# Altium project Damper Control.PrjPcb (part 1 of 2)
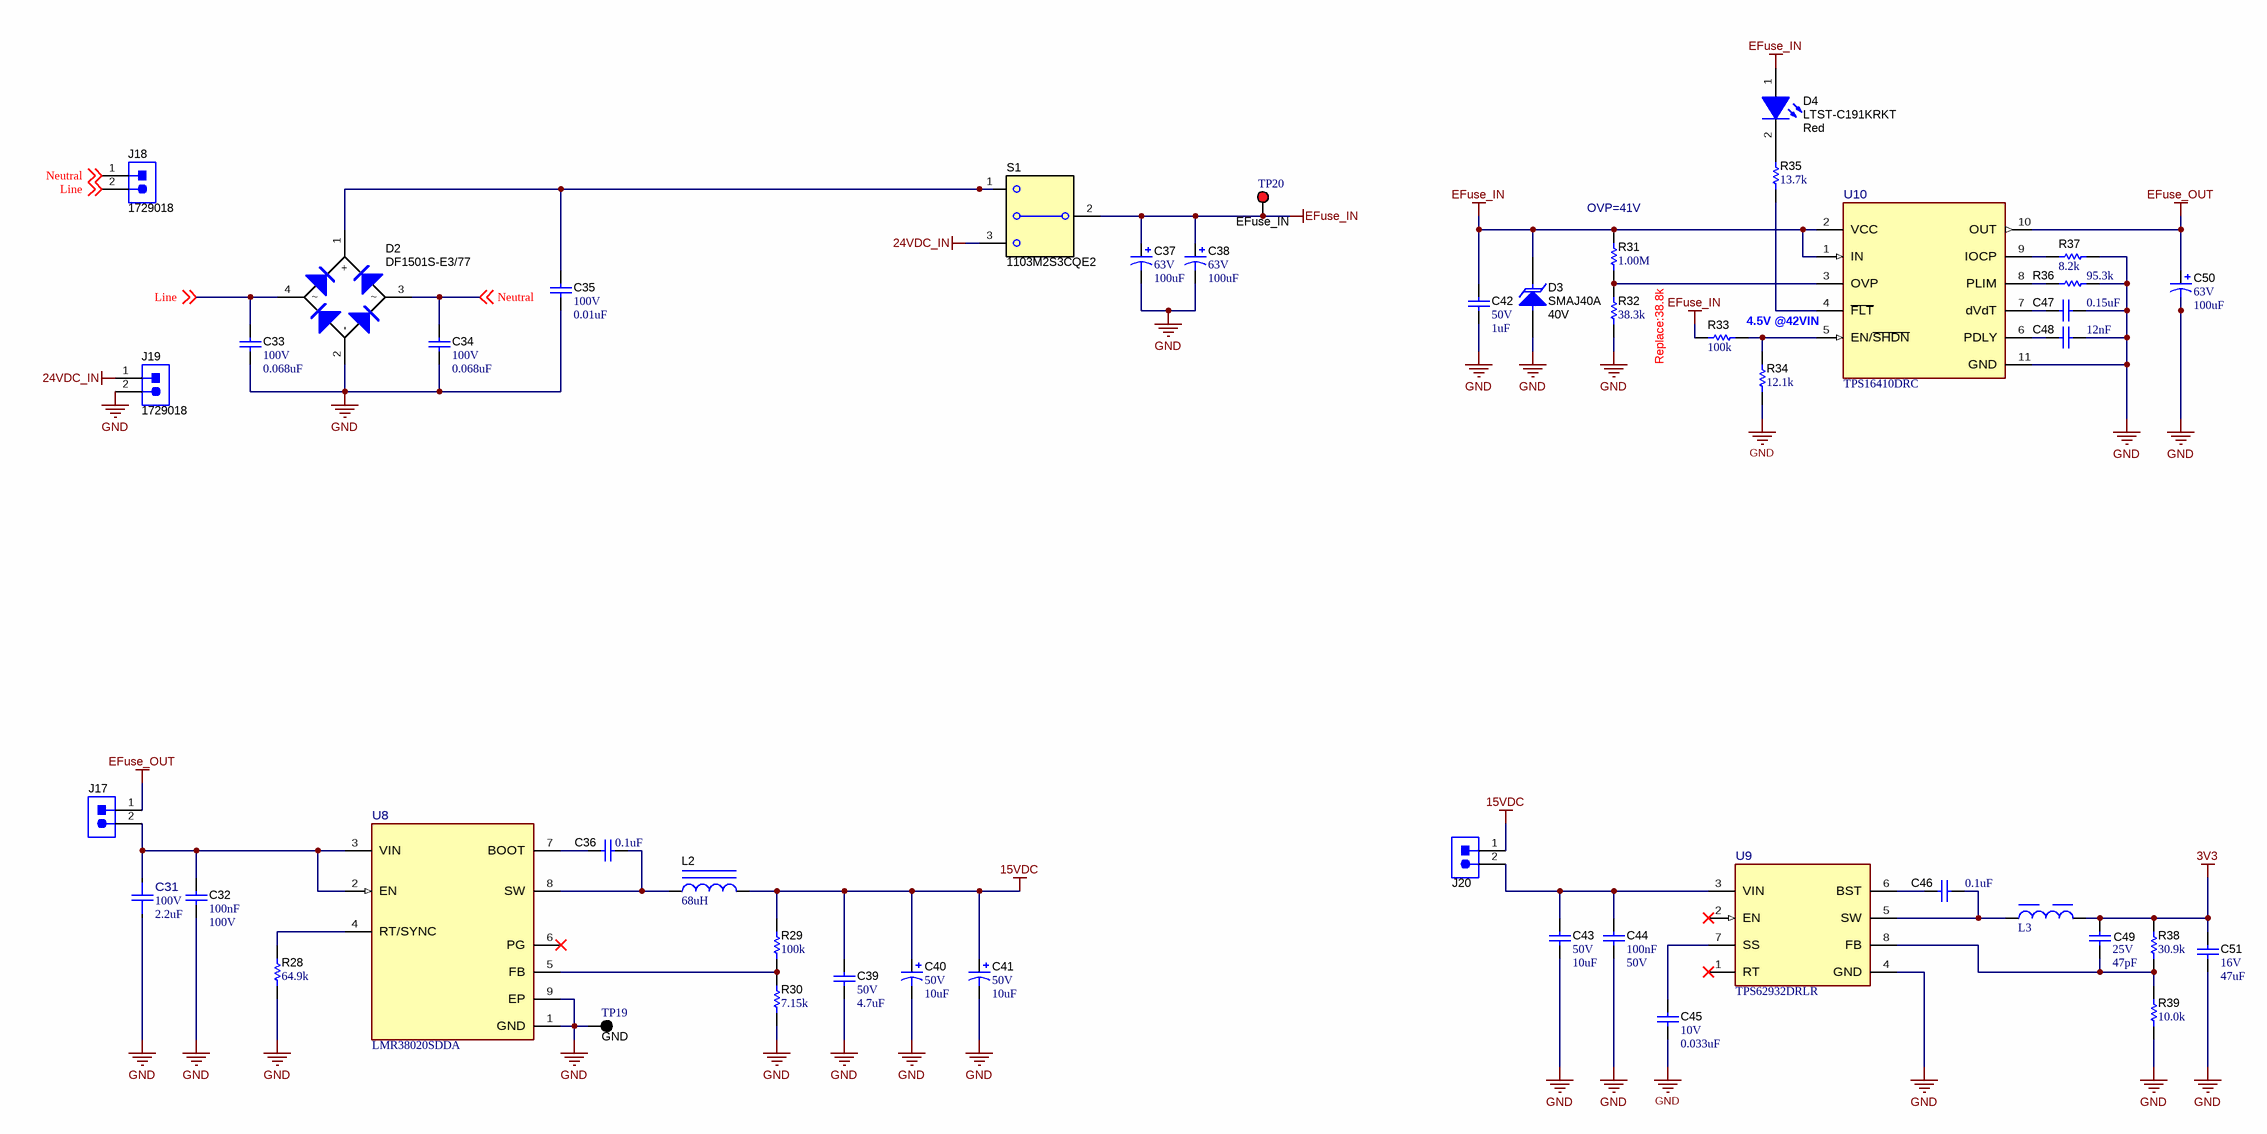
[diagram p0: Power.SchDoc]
CopyrightYear: 2018; PCB_Layout: Who did the Layout?; PCB_Rev: E1; PRJ_Customer: Public Release; PRJ_Engineer: Enter name of project lead; PRJ_Number: TIDA-010950; PRJ_Title: Damper and Electronic Expansion Valve Control with Position Sensing; SCH_Rev: E1; TechSupport: http://www.ti.com/support; TID: N/A
4 sheets, 208 parts. Net scope: global (net labels, ports and power ports of the same name join across sheets).
Board file: Damper Control.PcbDoc
Sheets:
  Power.SchDoc
  Damper Control_BlankSheet.SchDoc
  Interface and Peripherals.SchDoc
  Damper Control_Hardware.SchDoc

## Sheet Power.SchDoc
size A2; Date: Not shown in title block; ApprovedBy: Not shown in title block; CheckedBy: Not shown in title block; Author: Not shown in title block; CompanyName: Not shown in title block; Engineer: Not shown in title block; Organization: Not shown in title block; Address1: Not shown in title block; Address2: Not shown in title block; Address3: Not shown in title block; Address4: Not shown in title block; DocumentNumber: 2; Revision: Use project parameter SCH_Rev; SheetNumber: 2; SheetTotal: 5; PageSetup: Record=PageOptions¦CenterHorizontal=True¦CenterVertical=True¦PrintScale=0.69¦XCorrection=1.00¦YCorrection=1.00¦PrintKind=0¦BorderSize=5000000¦LeftOffset=0¦BottomOffset=0¦Orientation=2¦PaperLength=1000¦PaperWidth=1000¦Scale=100¦PaperSource=15¦PrintQuality=600¦MediaType=1¦DitherType=10¦PaperKind=Letter¦PrintScaleMode=1

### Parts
C31  VDC_V: 100V  ValueDisplayed: 2.2uF  [FP-C3225X7R2A225K230AB_1210-MFG]  (hidden comment: C3225X7R2A225K230AB)
C32  Cap_F: 100nF  VDC_V: 100V  [0805_HV]  (hidden comment: C2012X7R2A104K125AA)
C33  VDC_V: 100V  ValueDisplayed: 0.068uF  [0603]  (hidden comment: C1608X7S2A683K080AB)
C34  VDC_V: 100V  ValueDisplayed: 0.068uF  [0603]  (hidden comment: C1608X7S2A683K080AB)
C35  VDC_V: 100V  ValueDisplayed: 0.01uF  [0402]  (hidden comment: CGA2B3X7S2A103K050BB)
C36  ValueDisplayed: 0.1uF  [0402]  (hidden comment: GRM155R71C104KA88D)
C37  VDC_V: 63V  ValueDisplayed: 100uF  [SM_RADIAL_G]  (hidden comment: EEE-FK1J101P)
C38  VDC_V: 63V  ValueDisplayed: 100uF  [SM_RADIAL_G]  (hidden comment: EEE-FK1J101P)
C39  VDC_V: 50V  ValueDisplayed: 4.7uF  [0805_HV]  (hidden comment: C2012X5R1H475K125AB)
C40  VDC_V: 50V  ValueDisplayed: 10uF  [CAPSMT_62_F61]  (hidden comment: 50SVPF10M)
C41  VDC_V: 50V  ValueDisplayed: 10uF  [CAPSMT_62_F61]  (hidden comment: 50SVPF10M)
C42  VDC_V: 50V  ValueDisplayed: 1uF  [0603]  (hidden comment: C1608X5R1H105K080AB)
C43  VDC_V: 50V  ValueDisplayed: 10uF  [1206_180]  (hidden comment: C3216X5R1H106K160AB)
C44  Cap_F: 100nF  VDC_V: 50V  [0603]  (hidden comment: CGA3E2X7R1H104K080AA)
C45  VDC_V: 10V  ValueDisplayed: 0.033uF  [0402]  (hidden comment: GRM155R71A333KA01D)
C46  ValueDisplayed: 0.1uF  [0402]  (hidden comment: GRM155R71A104KA01D)
C47  ValueDisplayed: 0.15uF  [0603]  (hidden comment: C1608X5R1H154K080AB)
C48  Cap_F: 12nF  [0603]  (hidden comment: GRM188R71H123KA01D)
C49  VDC_V: 25V  ValueDisplayed: 47pF  [0201_033]  (hidden comment: GRM0335C1E470JA01D)
C50  VDC_V: 63V  ValueDisplayed: 100uF  [CAPSMT_62_KE0]  (hidden comment: EMVH630ARA101MKE0S)
C51  VDC_V: 16V  ValueDisplayed: 47uF  [1210_270]  (hidden comment: GRM32ER61C476KE15L)
D2  DF1501S-E3/77  [DF-S]
D3  SMAJ40A  value 40V  [SMA]
D4  LTST-C191KRKT  value Red  [LTST-C191_Red]
J17  M20-8770246  [Harwin_M20-87702]  (value not drawn)
J18  1729018  [Phoenix_1729018]
J19  1729018  [Phoenix_1729018]
J20  M20-8770246  [Harwin_M20-87702]  (value not drawn)
L2  ValueDisplayed: 68uH  [MSS1210]  (hidden comment: MSS1210-683ME)
L3  744325780  [WE-HCI_1050]  (value not drawn)
R28  ValueDisplayed: 64.9k  [0603]  (hidden comment: CRCW060364K9FKEA)
R29  ValueDisplayed: 100k  [0402]  (hidden comment: CRCW0402100KFKED)
R30  ValueDisplayed: 7.15k  [0402]  (hidden comment: CRCW04027K15FKED)
R31  ValueDisplayed: 1.00M  [0603]  (hidden comment: MCT06030C1004FP500)
R32  ValueDisplayed: 38.3k  [0402]  (hidden comment: CRCW040238K3FKED)
R33  ValueDisplayed: 100k  [0603]  (hidden comment: CRCW0603100KJNEA)
R34  ValueDisplayed: 12.1k  [0603]  (hidden comment: CRCW060312K1FKEA)
R35  ValueDisplayed: 13.7k  [0805_HV]  (hidden comment: CRCW080513K7FKEA)
R36  ValueDisplayed: 95.3k  [0603]  (hidden comment: CRCW060395K3FKEA)
R37  ValueDisplayed: 8.2k  [0603]  (hidden comment: CRCW06038K20JNEA)
R38  ValueDisplayed: 30.9k  [0402]  (hidden comment: CRCW040230K9FKED)
R39  ValueDisplayed: 10.0k  [0402]  (hidden comment: CRCW040210K0FKED)
S1  1103M2S3CQE2  [SW_1103M2S3CQE2]
TP19  GND  [Keystone5001]
TP20  EFuse_IN  [Keystone5000]
U8  LMR38020SDDA  [DDA0008E-MFG]
U9  TPS62932DRLR  [DRL0008A-MFG]
U10  TPS16410DRC  [DRC0010J-MFG]

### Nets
3V3: C49.1 C51.1 L3.2 R38.2
15VDC: C39.1 C40.1(+) C41.1(+) J20.1 L2.2 R29.2
24VDC_IN: J19.1 S1.3
EFuse_IN: C37.1(+) C38.1(+) C42.1 D3.1(K) D4.1(A) R31.2 R33.1 S1.2(COM) TP20.1 U10.1(IN) U10.2(VCC)
EFuse_OUT: C50.1(+) J17.1 U10.10(OUT)
GND: C31.1 C32.2 C33.2 C34.2 C35.2 C37.2(-) C38.2(-) C39.2 C40.2(-) C41.2(-) C42.2 C43.2 C44.2 C45.2 C47.1 C48.1 C50.2(-) C51.2 D2.2(-) D3.2(A) J19.2 R28.1 R30.1 R32.1 R34.1 R36.2 R37.2 R39.1 TP19.1 U8.1(GND) U8.9(EP) U9.4(GND) U10.11(GND)
Line: C33.1 D2.4 J18.2 ; off-sheet Line
Neutral: C34.1 D2.3 J18.1 ; off-sheet Neutral
NetC31_2: C31.2 C32.1 J17.2 U8.2(EN) U8.3(VIN)
NetC35_1: C35.1 D2.1(+) S1.1
NetC36_1: C36.1 L2.1 U8.8(SW)
NetC36_2: C36.2 U8.7(BOOT)
NetC43_1: C43.1 C44.1 J20.2 U9.3(VIN)
NetC45_1: C45.1 U9.7(SS)
NetC46_1: C46.1 L3.1 U9.5(SW)
NetC46_2: C46.2 U9.6(BST)
NetC47_2: C47.2 U10.7(dVdT)
NetC48_2: C48.2 U10.6(PDLY)
NetC49_2: C49.2 R38.1 R39.2 U9.8(FB)
NetD4_2: D4.2(K) R35.2
NetR28_2: R28.2 U8.4(RT/SYNC)
NetR29_1: R29.1 R30.2 U8.5(FB)
NetR31_1: R31.1 R32.2 U10.3(OVP)
NetR33_2: R33.2 R34.2 U10.5(EN/~{SHDN})
NetR35_1: R35.1 U10.4(~{FLT})
NetR36_1: R36.1 U10.8(PLIM)
NetR37_1: R37.1 U10.9(IOCP)

Not connected (* = marked no-connect by the designer): U8 6(PG)*; U9 1(RT)* 2(EN)*

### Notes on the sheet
- (near R31) OVP=41V
- (near R33) 4.5V @42VIN
- Replace:38.8k

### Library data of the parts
C31 = CMP-0095533-2: CAP, CERM, 2.2 uF, 100 V, +/- 10%, X7R, 1210; Manufacturer: TDK; AEC Qualified: No; Value: 2.2µF; Tolerance_%: 0.1%; TempCo: 0.15; SizeZ_mm: 2.5mm
C32 = CMP-0007886-2: CAP, CERM, 0.1 uF, 100 V, +/- 10%, X7R, 0805; Manufacturer: TDK; TaMin_C: -55°C; ESR_ohm: 20.726m; Polarized: N; SizeAreaWB_mm2: 6.75; Value1: 0.020726 ohm; U/M: EA; Value: 0.1uF; TaMax_C: 125°C; SizeZ_mm: 1.45; SizeX_mm: 2; SizeY_mm: 1.25; Cap_Case: 0805; SizeArea_mm2: 2.5; IRMS_A: 1.456A; AEC Category: Q200
C33 C34 = CMP-0007061-4: CAP, CERM, 0.068 uF, 100 V, +/- 10%, X7S, 0603; Manufacturer: TDK; TaMin_C: -55°C; ESR_ohm: 74.084m; Polarized: N; SizeAreaWB_mm2: 4.68; Value1: 0.074084 ohm; U/M: EA; TaMax_C: 125°C; SizeZ_mm: 1; SizeX_mm: 1.6; SizeY_mm: 0.8; SizeArea_mm2: 1.28; Cap_F: 68nF; IRMS_A: 619.09mA; AEC Category: Q200
C35 = CMP-0006333-2: CAP, CERM, 0.01 uF, 100 V, +/- 10%, X7S, AEC-Q200 Grade 1, 0402; Manufacturer: TDK; TaMin_C: -55°C; ESR_ohm: 0.4102; Polarized: N; SizeAreaWB_mm2: 3; Value1: 0.410191 ohm; U/M: EA; Value: 0.01uF; TaMax_C: 125°C; SizeZ_mm: 0.6; SizeX_mm: 1; SizeY_mm: 0.5; AEC Qualified: Y; Cap_F: 10nF; IRMS_A: 291.729mA; AEC Category: Q200
C36 = CMP-0006641-2: CAP, CERM, 0.1 uF, 16 V, +/- 10%, X7R, 0402; Manufacturer: MuRata; TaMin_C: -55°C; Polarized: N; SizeAreaWB_mm2: 3; Value1: Unknown; U/M: EA; Value: 0.1uF; TaMax_C: 125°C; SizeZ_mm: 0.6; SizeX_mm: 1; SizeY_mm: 0.5; Value2: 16V; Cap_F: 100nF; AEC Category: Q200
C37 C38 = CMP-0011188-2: CAP, AL, 100 uF, 63 V, +/- 20%, 0.35 ohm, AEC-Q200 Grade 2, SMD; Manufacturer: Panasonic; TaMin_C: -55°C; ESR_ohm: 0.35; Polarized: Y; SizeAreaWB_mm2: 172.2; U/M: EA; Value: 100uF; TaMax_C: 105°C; SizeZ_mm: 10.2; SizeX_mm: 12; SizeY_mm: 10.3; Cap_Case: G; SizeArea_mm2: 123.6; CompType: Capacitor; Cap_F: 100µF; IRMS_A: 400mA; AEC Grade: 2; AEC Category: Q200
C39 = CMP-0007840-2: CAP, CERM, 4.7 uF, 50 V, +/- 10%, X5R, 0805; Manufacturer: TDK; TaMin_C: -55°C; ESR_ohm: 2.346m; Polarized: N; SizeAreaWB_mm2: 6.75; Value1: 0.002346 ohm; U/M: EA; Value: 4.7uF; TaMax_C: 85°C; SizeZ_mm: 1.45; SizeX_mm: 2; SizeY_mm: 1.25; Cap_Case: 0805; SizeArea_mm2: 2.5; Cap_F: 4.7µF; IRMS_A: 4.2602A; AEC Category: Q200
C40 C41 = CMP-0012141-3: CAP, Aluminum Polymer, 10 uF, 50 V, +/- 20%, 0.04 ohm, F61 SMD; Manufacturer: Panasonic; TaMin_C: -55°C; ESR_ohm: 40m; Polarized: Y; SizeAreaWB_mm2: 73.96; Value: 10uF; TaMax_C: 105°C; SizeZ_mm: 5.8; SizeX_mm: 6.6; SizeArea_mm2: 43.56; CompType: Capacitor; Cap_F: 10µF; IRMS_A: 2.5A; AEC Category: Q200
C42 = CMP-0007011-5: CAP, CERM, 1 uF, 50 V, +/- 10%, X5R, 0603; Manufacturer: TDK; TaMin_C: -55°C; ESR_ohm: 5.522m; Polarized: N; SizeAreaWB_mm2: 4.68; Value1: 0.005522 ohm; U/M: EA; Value: 1uF; TaMax_C: 85°C; SizeZ_mm: 1; SizeX_mm: 1.6; SizeY_mm: 0.8; SizeArea_mm2: 1.28; Cap_F: 1µF; IRMS_A: 2.2162A; AEC Category: Q200
C43 = CMP-0008658-2: CAP, CERM, 10 uF, 50 V, +/- 10%, X5R, 1206; Manufacturer: TDK; TaMin_C: -55°C; ESR_ohm: 2.229m; Polarized: N; SizeAreaWB_mm2: 10.92; Value1: 0.002229 ohm; U/M: EA; Value: 10uF; TaMax_C: 85°C; SizeZ_mm: 1.8; SizeX_mm: 3.2; SizeY_mm: 1.6; SizeArea_mm2: 5.12; Cap_F: 10µF; IRMS_A: 4.8593A; AEC Category: Q200
C44 = CMP-0007078-4: CAP, CERM, 0.1 uF, 50 V, +/- 10%, X7R, AEC-Q200 Grade 1, 0603; Manufacturer: TDK; TaMin_C: -55°C; ESR_ohm: 29.6m; Polarized: N; SizeAreaWB_mm2: 4.68; Value1: 0.0296 ohm; U/M: EA; Value: 0.1uF; TaMax_C: 125°C; SizeZ_mm: 1; SizeX_mm: 1.6; SizeY_mm: 0.8; SizeArea_mm2: 1.28; AEC Qualified: Y; IRMS_A: 971.99mA; AEC Category: Q200
C45 = CMP-0006632-2: CAP, CERM, 0.033 uF, 10 V, +/- 10%, X7R, 0402; Manufacturer: MuRata; TaMin_C: -55°C; Polarized: N; SizeAreaWB_mm2: 3; Value1: Unknown; U/M: EA; TaMax_C: 125°C; SizeZ_mm: 0.6; SizeX_mm: 1; SizeY_mm: 0.5; Cap_F: 33nF; AEC Category: Q200
C46 = CMP-0006629-2: CAP, CERM, 0.1 uF, 10 V, +/- 10%, X7R, 0402; Manufacturer: MuRata; TaMin_C: -55°C; Polarized: N; SizeAreaWB_mm2: 3; Value1: Unknown; U/M: EA; Value: 0.1uF; TaMax_C: 125°C; SizeZ_mm: 0.6; SizeX_mm: 1; SizeY_mm: 0.5; Value2: 10V; Cap_F: 100nF; AEC Category: Q200
C47 = CMP-0007012-5: CAP, CERM, 0.15 uF, 50 V, +/- 10%, X5R, 0603; Manufacturer: TDK; TaMin_C: -55°C; ESR_ohm: 28.863m; Polarized: N; SizeAreaWB_mm2: 4.68; Value1: 0.028863 ohm; U/M: EA; Value: 0.15uF; TaMax_C: 85°C; SizeZ_mm: 1; SizeX_mm: 1.6; SizeY_mm: 0.8; Value2: 50V; SizeArea_mm2: 1.28; Cap_F: 150nF; IRMS_A: 978.809mA; AEC Category: Q200
C48 = CMP-0007436-4: CAP, CERM, 0.012 uF, 50 V, +/- 10%, X7R, 0603; Manufacturer: MuRata; TaMin_C: -55°C; Polarized: N; SizeAreaWB_mm2: 4.68; Value1: Unknown; U/M: EA; TaMax_C: 125°C; SizeZ_mm: 1; SizeX_mm: 1.6; SizeY_mm: 0.8; Value2: 50V; SizeArea_mm2: 1.28; AEC Category: Q200
C49 = CMP-0009662-3: CAP, CERM, 47 pF, 25 V, +/- 5%, C0G/NP0, 0201; Manufacturer: MuRata; TaMin_C: -55°C; Polarized: N; SizeAreaWB_mm2: 2.08; Value1: Unknown; U/M: EA; Value: 47pF; TaMax_C: 125°C; SizeZ_mm: 0.33; SizeX_mm: 0.6; SizeY_mm: 0.3; Cap_Case: 0201; SizeArea_mm2: 0.18; AEC Category: Q200
C50 = CMP-0011330-2: CAP, AL, 100 uF, 63 V, +/- 20%, 0.25 ohm, SMD; Manufacturer: Chemi-Con; TaMin_C: -40°C; ESR_ohm: 0.25; Polarized: Y; SizeAreaWB_mm2: 225; U/M: EA; Value: 100uF; TaMax_C: 125°C; SizeZ_mm: 13.5; SizeX_mm: 13; Cap_Case: KE0; SizeArea_mm2: 169; CompType: Capacitor; Cap_F: 100µF; IRMS_A: 500mA; AEC Category: Q200
C51 = CMP-0009211-2: CAP, CERM, 47 uF, 16 V, +/- 10%, X5R, 1210; Manufacturer: MuRata; TaMin_C: -55°C; Polarized: N; SizeAreaWB_mm2: 14.7; Value1: Unknown; U/M: EA; Value: 47uF; TaMax_C: 85°C; SizeZ_mm: 2.7; SizeX_mm: 3.2; SizeY_mm: 2.5; Cap_Case: 1210; SizeArea_mm2: 8; Cap_F: 47µF; AEC Category: Q200
D2 = CMP-0029239-3: Diode, Switching-Bridge, 100 V, 1.5 A, DF-S; Manufacturer: Vishay-Semiconductor; Green_REACh: Incomplete; Value1: 1.5A; SizeAreaWB_mm2: 98.794; Vr_V: 100V; SizeZ_mm: 3.4; AEC Category: Q101; Value: 100V; TJmax_C: 150°C; Vf_V: 1.1V; SizeArea_mm2: 62.974; SizeX_mm: 7.4; SizeY_mm: 8.51; Green_Lifecycle: Not Set
D3 = CMP-0084964-1: Diode, TVS, Uni, 40 V, 64.5 Vc, 400 W, 6.2 A, SMA; Manufacturer: Littelfuse; Ipp: 6.2A; Ppk: 400W; Vbr_Min: 44.4V; AEC Category: Q101; SizeAreaWB_mm2: 37.3428; SizeX_mm: 5.59; SizeArea_mm2: 16.3228; AEC Qualified: N; Value1: 64.5V; SizeY_mm: 2.92; RJA_CperW: 120; SizeZ_mm: 2.87; Vbr_Max: 49.1V
D4 = CMP-0002950-3: LED, Red, SMD; Manufacturer: Lite-On; Value2: 2V; Type: AlInGaP; Ir_A: 10µA; Angle: 130; Value1: 0.075W; Vr_V: 5V; Tjmax_C: 85°C; Power_TotalModule: 75mW; Io_A: 20mA
J17 J20 = CMP-0075288-1: Header, 2.54mm, 2x1, Tin,  SMT; Manufacturer: Harwin; CNHeader: True; Current_A: 3A; Shrouded: N; Gender: Male; Voltage_V: 250V; Row_Count: 1; Pitch_mm: 2.54; CT: False; Cert_UL: Y
J18 J19 = CMP-0055486-1: TERM BLOCK 2POS 5mm, TH; Manufacturer: Phoenix Contact; CT: TRUE; Green_REACh: Incomplete; CompType: Terminal Block; CNHeader: FALSE; Green_Lifecycle: Not Set
L2 = CMP-0061458-2: Inductor, Shielded, Ferrite, 68 uH, 4.3 A, 0.074 ohm, SMD; Manufacturer: Coilcraft; Isat: 4.9A @ 30% inductance drop; Irms: 4.3A @ 40C rise; Green_Lifecycle: Not Set; SizeAreaWB_mm2: 204.49; DCR_ohm: 74m; Green_REACh: Incomplete; Value: 68uH; Imax_A: 4.3A; SizeZ_mm: 10; SizeX_mm: 12.3; SizeArea_mm2: 151.29; Ind_H: 68µH; AEC Category: Q200
L3 = CMP-0098677-1: WE-HCI SMT Flat Wire High Current Inductor, size 1050, 7.8uH, 10.7A, 13.6mOhm; Manufacturer: Wurth Elektronik; Material: Superflux; Case/Size Code: 1050; Saturation Current: 9.5A; Self Resonant Frequency: 23MHz
R28 = CMP-0022544-4: RES, 64.9 k, 1%, 0.1 W, AEC-Q200 Grade 0, 0603; Manufacturer: Vishay-Dale; Power_W: 100mW; TempCo: 100 ppm/C; Value_Code: 64k9; Value: 64.9k; EIA_Code: E96; SizeX_mm: 1.6; SizeY_mm: 0.8; SizeZ_mm: 1; Value2: 0.1W; SizeArea_mm2: 1.28; AEC Qualified: Y; VDC_V: 75V; AEC Category: Q200; AEC Grade: 0
R29 = CMP-0025950-3: RES, 100 k, 1%, 0.063 W, AEC-Q200 Grade 0, 0402; Manufacturer: Vishay-Dale; Power_W: 63mW; TempCo: 100 ppm/C; Value: 100k; EIA_Code: E96; SizeX_mm: 1; SizeY_mm: 0.5; SizeZ_mm: 0.6; Value2: 0.063W; AEC Qualified: Y; VDC_V: 50V; AEC Category: Q200; AEC Grade: 0
R30 = CMP-0026553-2: RES, 7.15 k, 1%, 0.063 W, AEC-Q200 Grade 0, 0402; Manufacturer: Vishay-Dale; Power_W: 63mW; TempCo: 100 ppm/C; Value_Code: 7k15; Value: 7.15k; EIA_Code: E96; SizeX_mm: 1; SizeY_mm: 0.5; SizeZ_mm: 0.6; Value2: 0.063W; AEC Qualified: Y; VDC_V: 50V; AEC Category: Q200; AEC Grade: 0
R31 = CMP-0022731-2: RES, 1.00 M, 1%, 0.125 W, 0603; Manufacturer: Vishay/Beyschlag; Power_W: 125mW; TempCo: 50 ppm/C; Value_Code: 1M00; U/M: EA; Value: 1.00Meg; EIA_Code: E96; Res_ohm: 1M; SizeX_mm: 1.6; SizeY_mm: 0.8; SizeZ_mm: 1; Value2: 0.125W; SizeArea_mm2: 1.28; AEC Qualified: N; VDC_V: 75V; AEC Category: Q200
R32 = CMP-0026323-2: RES, 38.3 k, 1%, 0.063 W, AEC-Q200 Grade 0, 0402; Manufacturer: Vishay-Dale; Power_W: 63mW; TempCo: 100 ppm/C; Value_Code: 38k3; Value: 38.3k; EIA_Code: E96; SizeX_mm: 1; SizeY_mm: 0.5; SizeZ_mm: 0.6; Value2: 0.063W; AEC Qualified: Y; VDC_V: 50V; AEC Category: Q200; AEC Grade: 0
R33 = CMP-0025698-4: RES, 100 k, 5%, 0.1 W, AEC-Q200 Grade 0, 0603; Manufacturer: Vishay-Dale; Power_W: 100mW; TempCo: 200 ppm/C; Value: 100k; EIA_Code: E24; SizeX_mm: 1.6; SizeY_mm: 0.8; SizeZ_mm: 1; Value2: 0.1W; SizeArea_mm2: 1.28; AEC Qualified: Y; VDC_V: 75V; AEC Category: Q200; AEC Grade: 0
R34 = CMP-0022030-4: RES, 12.1 k, 1%, 0.1 W, AEC-Q200 Grade 0, 0603; Manufacturer: Vishay-Dale; Power_W: 100mW; TempCo: 100 ppm/C; Value_Code: 12k1; Value: 12.1k; EIA_Code: E96; SizeX_mm: 1.6; SizeY_mm: 0.8; SizeZ_mm: 1; Value2: 0.1W; SizeArea_mm2: 1.28; AEC Qualified: Y; VDC_V: 75V; AEC Category: Q200; AEC Grade: 0
R35 = CMP-0020887-3: RES, 13.7 k, 1%, 0.125 W, AEC-Q200 Grade 0, 0805; Manufacturer: Vishay-Dale; Power_W: 125mW; TempCo: 100 ppm/C; Value_Code: 13k7; Value: 13.7k; EIA_Code: E96; SizeX_mm: 2; SizeY_mm: 1.25; SizeZ_mm: 1.45; Value2: 0.125W; SizeArea_mm2: 2.5; AEC Qualified: Y; VDC_V: 150V; AEC Category: Q200; AEC Grade: 0
R36 = CMP-0022659-4: RES, 95.3 k, 1%, 0.1 W, AEC-Q200 Grade 0, 0603; Manufacturer: Vishay-Dale; Power_W: 100mW; TempCo: 100 ppm/C; Value_Code: 95k3; Value: 95.3k; EIA_Code: E96; SizeX_mm: 1.6; SizeY_mm: 0.8; SizeZ_mm: 1; Value2: 0.1W; SizeArea_mm2: 1.28; AEC Qualified: Y; VDC_V: 75V; AEC Category: Q200; AEC Grade: 0
R37 = CMP-0025862-4: RES, 8.2 k, 5%, 0.1 W, AEC-Q200 Grade 0, 0603; Manufacturer: Vishay-Dale; Power_W: 100mW; TempCo: 200 ppm/C; Value_Code: 8k20; Value: 8.2k; EIA_Code: E24; SizeX_mm: 1.6; SizeY_mm: 0.8; SizeZ_mm: 1; Value2: 0.1W; SizeArea_mm2: 1.28; AEC Qualified: Y; VDC_V: 75V; AEC Category: Q200; AEC Grade: 0
R38 = CMP-0026285-2: RES, 30.9 k, 1%, 0.063 W, AEC-Q200 Grade 0, 0402; Manufacturer: Vishay-Dale; Power_W: 63mW; TempCo: 100 ppm/C; Value_Code: 30k9; Value: 30.9k; EIA_Code: E96; SizeX_mm: 1; SizeY_mm: 0.5; SizeZ_mm: 0.6; Value2: 0.063W; AEC Qualified: Y; VDC_V: 50V; AEC Category: Q200; AEC Grade: 0
R39 = CMP-0025958-3: RES, 10.0 k, 1%, 0.063 W, AEC-Q200 Grade 0, 0402; Manufacturer: Vishay-Dale; Power_W: 63mW; TempCo: 100 ppm/C; Value_Code: 10k0; Value: 10.0k; EIA_Code: E96; Res_ohm: 10k; SizeX_mm: 1; SizeY_mm: 0.5; SizeZ_mm: 0.6; Value2: 0.063W; AEC Qualified: Y; VDC_V: 50V; AEC Category: Q200; AEC Grade: 0
S1 = CMP-0002255-1: Switch, Slide, SPDT, On-Off-On, 1 Pos, 6A, 120 VAC, 28 VDC, TH; Manufacturer: C&K Components; CurrentRating_mA: 6kA; PositionCount: 1; VDC_V: 28V
TP19 = CMP-0055138-2: Test Point, Miniature, Black, TH; Manufacturer: Keystone Electronics; ContactFinish: Silver; CNHeader: FALSE; Green_Lifecycle: Active; Green_REACh: Passed; CT: TRUE
TP20 = CMP-0055137-2: Test Point, Miniature, Red, TH; Manufacturer: Keystone Electronics; Green_REACh: Passed; Green_Lifecycle: Active; ContactFinish: Silver; CNHeader: FALSE; CT: TRUE
U8 = CMP-0094072-1: SIMPLE SWITCHER 4.2-V to 80-V, 2-A Synchronous Buck Converter; Manufacturer: Texas Instruments; Switching Frequency: 200-1100kHz; Max Duty Cycle: 98%; Output Voltage: 1-75V; Max Supply Voltage: 80V; Standoff Height: 0mm; Nominal Supply Current: 40uA; AEC Qualified: No; TJmax_C: +150°C; Output Type: AdjustableProgrammable; SizeZ_mm: 1.7mm; Number Of Outputs: 1; Min Supply Voltage: 4.2V
U9 = CMP-0094457-2: 3.8-V to 30-V, 2-A Synchronous Buck Converter in SOT583 Package; Manufacturer: Texas Instruments; SizeZ_mm: 0.6mm; Max Duty Cycle: 98%; Min Supply Voltage: 3.8V; Output Type: AdjustableProgrammable; Number Of Outputs: 1; AEC Qualified: No; AEC Category: Q200; Nominal Supply Current: 12uA; CompType: IC; Standoff Height: 0mm; TJmax_C: +150°C; Switching Frequency: 310-2100kHz; Max Supply Voltage: 30V; Output Voltage: 0.8-22V
U10 = CMP-0093898-1: Manufacturer: Texas Instruments; Standoff Height: 0mm; SizeZ_mm: 1mm

## Sheet Damper Control_BlankSheet.SchDoc
size 431 x 279 mm; Date: Not shown in title block; ApprovedBy: Not shown in title block; CheckedBy: Not shown in title block; Author: Not shown in title block; CompanyName: Not shown in title block; Engineer: Not shown in title block; Organization: Not shown in title block; Address1: Not shown in title block; Address2: Not shown in title block; Address3: Not shown in title block; Address4: Not shown in title block; DocumentNumber: 3; Revision: Use project parameter SCH_Rev; SheetNumber: 3; SheetTotal: 5; PageSetup: Record=PageOptions¦CenterHorizontal=True¦CenterVertical=True¦PrintScale=1.00¦XCorrection=1.00¦YCorrection=1.00¦PrintKind=0¦BorderSize=5000000¦LeftOffset=0¦BottomOffset=0¦Orientation=2¦PaperLength=1000¦PaperWidth=1000¦Scale=100¦PaperSource=15¦PrintQuality=600¦MediaType=1¦DitherType=10¦PaperKind=Letter¦PrintScaleMode=1
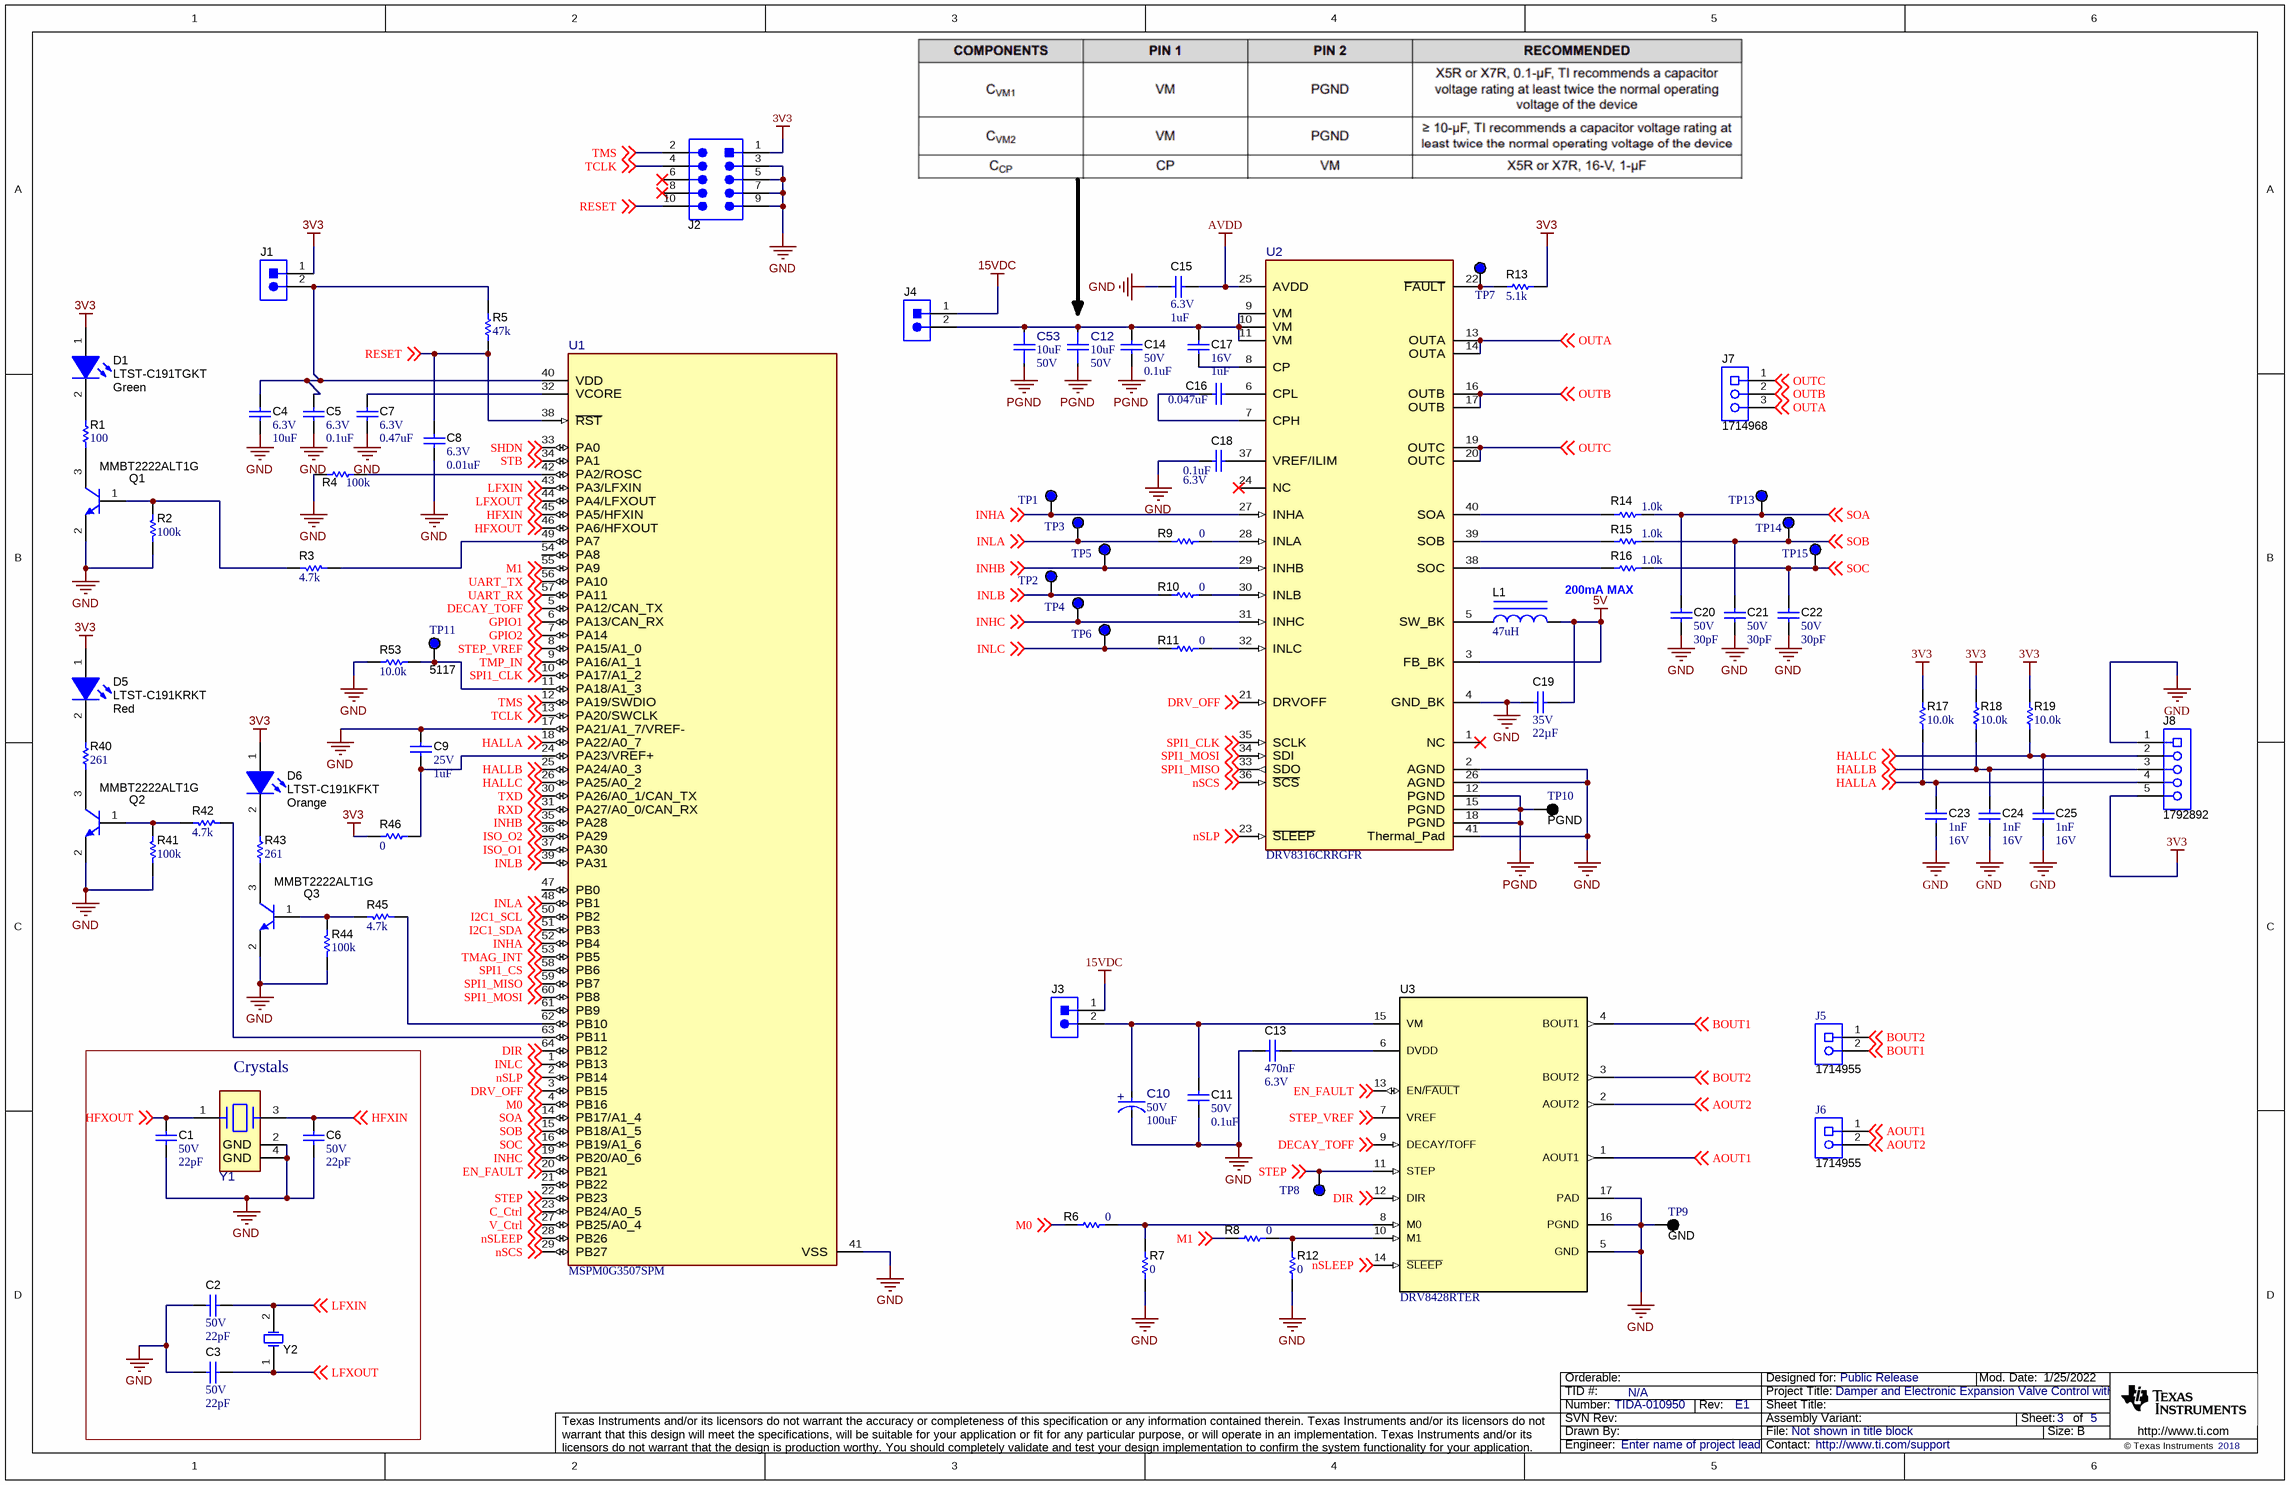
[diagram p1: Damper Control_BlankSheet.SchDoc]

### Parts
C1  VDC_V: 50V  ValueDisplayed: 22pF  [0402]  (hidden comment: GRM1555C1H220JA01D)
C2  VDC_V: 50V  ValueDisplayed: 22pF  [0402]  (hidden comment: GRM1555C1H220JA01D)
C3  VDC_V: 50V  ValueDisplayed: 22pF  [0402]  (hidden comment: GRM1555C1H220JA01D)
C4  VDC_V: 6.3V  ValueDisplayed: 10uF  [0603]  (hidden comment: GRM188R60J106ME84)
C5  VDC_V: 6.3V  ValueDisplayed: 0.1uF  [0402]  (hidden comment: GRM155R60J104KA01D)
C6  VDC_V: 50V  ValueDisplayed: 22pF  [0402]  (hidden comment: GRM1555C1H220JA01D)
C7  VDC_V: 6.3V  ValueDisplayed: 0.47uF  [0402]  (hidden comment: GRM155R60J474KE19D)
C8  VDC_V: 6.3V  ValueDisplayed: 0.01uF  [0402]  (hidden comment: GRM155R60J103KA01D)
C9  VDC_V: 25V  ValueDisplayed: 1uF  [0603]  (hidden comment: C1608X5R1E105K080AC)
C10  VDC_V: 50V  ValueDisplayed: 100uF  [FP-107AXZ050M_RADIAL-MFG]  (hidden comment: 107AXZ050M)
C11  VDC_V: 50V  ValueDisplayed: 0.1uF  [0603]  (hidden comment: C1608X5R1H104K080AA)
C12  ValueDisplayed: 10uF  VDC_V: 50V  [FP-GRM21BR61H106ME43L_0805-MFG]  (hidden comment: GRM21BR61H106ME43L)
C13  Cap_F: 470nF  VDC_V: 6.3V  [0603]  (hidden comment: GRM188R70J474KA01D)
C14  VDC_V: 50V  ValueDisplayed: 0.1uF  [0603]  (hidden comment: C1608X5R1H104K080AA)
C15  VDC_V: 6.3V  ValueDisplayed: 1uF  [0402]  (hidden comment: GRM155R60J105KE19D)
C16  ValueDisplayed: 0.047uF  [0402]  (hidden comment: GRM155R61H473ME14D)
C17  VDC_V: 16V  ValueDisplayed: 1uF  [0603]  (hidden comment: C0603C105K4PACTU)
C18  VDC_V: 6.3V  ValueDisplayed: 0.1uF  [0402]  (hidden comment: GRM155R60J104KA01D)
C19  VDC_V: 35V  ValueDisplayed: 22µF  [0805_HV]  (hidden comment: NMC0805X5R226M35TRPLPF)
C20  VDC_V: 50V  ValueDisplayed: 30pF  [0603]  (hidden comment: GRM1885C1H300JA01D)
C21  VDC_V: 50V  ValueDisplayed: 30pF  [0603]  (hidden comment: GRM1885C1H300JA01D)
C22  VDC_V: 50V  ValueDisplayed: 30pF  [0603]  (hidden comment: GRM1885C1H300JA01D)
C23  Cap_F: 1nF  VDC_V: 16V  [0603L]  (hidden comment: 885012206034)
C24  Cap_F: 1nF  VDC_V: 16V  [0603L]  (hidden comment: 885012206034)
C25  Cap_F: 1nF  VDC_V: 16V  [0603L]  (hidden comment: 885012206034)
C53  ValueDisplayed: 10uF  VDC_V: 50V  [FP-GRM21BR61H106ME43L_0805-MFG]  (hidden comment: GRM21BR61H106ME43L)
D1  LTST-C191TGKT  value Green  [LTST-C191_Green]
D5  LTST-C191KRKT  value Red  [LTST-C191_Red]
D6  LTST-C191KFKT  value Orange  [LTST-C191_Orange]
J1  M20-8770246  [Harwin_M20-87702]  (value not drawn)
J2  FTSH-105-01-F-DV-K  [Samtec_FTSH-105-01-x-DV-K]  (value not drawn)
J3  M20-8770246  [Harwin_M20-87702]  (value not drawn)
J4  M20-8770246  [Harwin_M20-87702]  (value not drawn)
J5  1714955  [Phoenix_1714955]
J6  1714955  [Phoenix_1714955]
J7  1714968  [Phoenix_1714968]
J8  1792892  [Phoenix_1792892]
L1  ValueDisplayed: 47uH  [NPI32C]  (hidden comment: NPI32C470MTRF)
Q1  MMBT2222ALT1G  [SOT-23]
Q2  MMBT2222ALT1G  [SOT-23]
Q3  MMBT2222ALT1G  [SOT-23]
R1  ValueDisplayed: 100  [0201]  (hidden comment: RC0201FR-07100RL)
R2  ValueDisplayed: 100k  [0201]  (hidden comment: RC0201FS-7D100KL)
R3  ValueDisplayed: 4.7k  [0201]  (hidden comment: RC0201JR-074K7L)
R4  ValueDisplayed: 100k  [0603]  (hidden comment: RT0603BRD07100KL)
R5  ValueDisplayed: 47k  [0402]  (hidden comment: CRCW040247K0JNED)
R6  ValueDisplayed: 0  [0603]  (hidden comment: CRCW06030000Z0EA)
R7  ValueDisplayed: 0  [0603]  (hidden comment: CRCW06030000Z0EA)
R8  ValueDisplayed: 0  [0603]  (hidden comment: CRCW06030000Z0EA)
R9  ValueDisplayed: 0  [0603]  (hidden comment: CRCW06030000Z0EA)
R10  ValueDisplayed: 0  [0603]  (hidden comment: CRCW06030000Z0EA)
R11  ValueDisplayed: 0  [0603]  (hidden comment: CRCW06030000Z0EA)
R12  ValueDisplayed: 0  [0603]  (hidden comment: CRCW06030000Z0EA)
R13  ValueDisplayed: 5.1k  [0603]  (hidden comment: CRCW06035K10JNEA)
R14  ValueDisplayed: 1.0k  [0603]  (hidden comment: CRCW06031K00JNEA)
R15  ValueDisplayed: 1.0k  [0603]  (hidden comment: CRCW06031K00JNEA)
R16  ValueDisplayed: 1.0k  [0603]  (hidden comment: CRCW06031K00JNEA)
R17  ValueDisplayed: 10.0k  [TNPW0603]  (hidden comment: TNPW060310K0BEEA)
R18  ValueDisplayed: 10.0k  [TNPW0603]  (hidden comment: TNPW060310K0BEEA)
R19  ValueDisplayed: 10.0k  [TNPW0603]  (hidden comment: TNPW060310K0BEEA)
R40  ValueDisplayed: 261  [0201]  (hidden comment: RC0201FR-07261RL)
R41  ValueDisplayed: 100k  [0201]  (hidden comment: RC0201FS-7D100KL)
R42  ValueDisplayed: 4.7k  [0201]  (hidden comment: RC0201JR-074K7L)
R43  ValueDisplayed: 261  [0201]  (hidden comment: RC0201FR-07261RL)
R44  ValueDisplayed: 100k  [0201]  (hidden comment: RC0201FS-7D100KL)
R45  ValueDisplayed: 4.7k  [0201]  (hidden comment: RC0201JR-074K7L)
R46  ValueDisplayed: 0  [0603]  (hidden comment: RC0603JR-070RL)
R53  ValueDisplayed: 10.0k  [TNPW0603]  (hidden comment: TNPW060310K0BEEA)
TP1  INHA  [Keystone5122]  (value not drawn)
TP2  INLB  [Keystone5122]  (value not drawn)
TP3  INLA  [Keystone5122]  (value not drawn)
TP4  INHC  [Keystone5122]  (value not drawn)
TP5  INHB  [Keystone5122]  (value not drawn)
TP6  INLC  [Keystone5122]  (value not drawn)
TP7  5122  [Keystone5122]  (value not drawn)
TP8  STEP  [Keystone5122]  (value not drawn)
TP9  GND  [Keystone5001]
TP10  PGND  [Keystone5001]
TP11  5117  [Keystone5117]
TP13  5122  [Keystone5122]  (value not drawn)
TP14  5122  [Keystone5122]  (value not drawn)
TP15  5122  [Keystone5122]  (value not drawn)
U1  MSPM0G3507SPM  [PM0064A-MFG]
U2  DRV8316CRRGFR  [RGF0040E-MFG]
U3  DRV8428RTER  [RTE0016J]
Y1  X1E0000210179  [FP-X1E0000210179_TSX-3225-MFG]  (value not drawn)
Y2  X1A0001410014  [Epson_FC-135]  (value not drawn)

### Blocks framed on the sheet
Crystals: C1-C3 C6 Y1 Y2

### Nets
3V3: D1.1(A) D5.1(A) D6.1(A) J1.1 J2.1 J8.5 R13.1 R17.2 R18.2 R19.2 R46.1
5V: C19.2 L1.2 U2.3(FB_BK)
15VDC: J3.1 J4.1
AVDD: C15.1 U2.25(AVDD)
GND: C1.2 C2.2 C3.2 C4.2 C5.2 C6.2 C7.2 C8.2 C9.2 C10.1(CATHODE) C11.2 C13.2 C15.2 C18.2 C19.1 C20.2 C21.2 C22.2 C23.2 C24.2 C25.2 J2.3 J2.5 J2.7 J2.9 J8.1 Q1.2(E) Q2.2(E) Q3.2(E) R2.1 R4.2 R7.1 R12.1 R41.1 R44.1 R53.2 TP9.1 U1.17(PA21/A1_7/VREF-) U1.41(VSS) U2.2(AGND) U2.4(GND_BK) U2.26(AGND) U2.41(Thermal_Pad) U3.5(GND) U3.16(PGND) U3.17(PAD) Y1.2(GND) Y1.4(GND)
PGND: C12.1 C14.2 C53.1 TP10.1 U2.12(PGND) U2.15(PGND) U2.18(PGND)
AOUT1: J6.1 U3.1(AOUT1) ; off-sheet AOUT1
AOUT2: J6.2 U3.2(AOUT2) ; off-sheet AOUT2
BOUT1: J5.2 U3.4(BOUT1) ; off-sheet BOUT1
BOUT2: J5.1 U3.3(BOUT2) ; off-sheet BOUT2
C_Ctrl: U1.23(PB24/A0_5) ; off-sheet C_Ctrl
DECAY_TOFF: U1.5(PA12/CAN_TX) U3.9(DECAY/TOFF) ; off-sheet DECAY_TOFF
DIR: U1.64(PB12) U3.12(DIR) ; off-sheet DIR
DRV_OFF: U1.3(PB15) U2.21(DRVOFF) ; off-sheet DRV_OFF
EN_FAULT: U1.20(PB21) U3.13(EN/~{FAULT}) ; off-sheet EN_FAULT
GPIO1: U1.6(PA13/CAN_RX) ; off-sheet GPIO1
GPIO2: U1.7(PA14) ; off-sheet GPIO2
HALLA: C23.1 J8.4 R17.1 U1.18(PA22/A0_7) ; off-sheet HALLA
HALLB: C24.1 J8.3 R18.1 U1.25(PA24/A0_3) ; off-sheet HALLB
HALLC: C25.1 J8.2 R19.1 U1.26(PA25/A0_2) ; off-sheet HALLC
HFXIN: C6.1 U1.45(PA5/HFXIN) Y1.3 ; off-sheet HFXIN
HFXOUT: C1.1 U1.46(PA6/HFXOUT) Y1.1 ; off-sheet HFXOUT
I2C1_SCL: U1.50(PB2) ; off-sheet I2C1_SCL
I2C1_SDA: U1.51(PB3) ; off-sheet I2C1_SDA
INHA: TP1.1 U1.52(PB4) U2.27(INHA) ; off-sheet INHA
INHB: TP5.1 U1.35(PA28) U2.29(INHB) ; off-sheet INHB
INHC: TP4.1 U1.19(PB20/A0_6) U2.31(INHC) ; off-sheet INHC
INLA: R9.1 TP3.1 U1.48(PB1) ; off-sheet INLA
INLB: R10.1 TP2.1 U1.39(PA31) ; off-sheet INLB
INLC: R11.1 TP6.1 U1.1(PB13) ; off-sheet INLC
ISO_O1: U1.37(PA30) ; off-sheet ISO_O1
ISO_O2: U1.36(PA29) ; off-sheet ISO_O2
LFXIN: C2.1 U1.43(PA3/LFXIN) Y2.2(OSC2) ; off-sheet LFXIN
LFXOUT: C3.1 U1.44(PA4/LFXOUT) Y2.1(OSC1) ; off-sheet LFXOUT
M0: R6.1 U1.4(PB16) ; off-sheet M0
M1: R8.1 U1.55(PA9) ; off-sheet M1
nSCS: U1.29(PB27) U2.36(~{SCS}) ; off-sheet nSCS
nSLEEP: U1.28(PB26) U3.14(~{SLEEP}) ; off-sheet nSLEEP
nSLP: U1.2(PB14) U2.23(~{SLEEP}) ; off-sheet nSLP
OUTA: J7.3 U2.13(OUTA) U2.14(OUTA) ; off-sheet OUTA
OUTB: J7.2 U2.16(OUTB) U2.17(OUTB) ; off-sheet OUTB
OUTC: J7.1 U2.19(OUTC) U2.20(OUTC) ; off-sheet OUTC
RESET: C8.1 J2.10 R5.1 U1.38(~{RST}) ; off-sheet RESET
RXD: U1.31(PA27/A0_0/CAN_RX) ; off-sheet RXD
SHDN: U1.33(PA0) ; off-sheet SHDN
SOA: C20.1 R14.2 TP13.1 U1.14(PB17/A1_4) ; off-sheet SOA
SOB: C21.1 R15.2 TP14.1 U1.15(PB18/A1_5) ; off-sheet SOB
SOC: C22.1 R16.2 TP15.1 U1.16(PB19/A1_6) ; off-sheet SOC
SPI1_CLK: U1.10(PA17/A1_2) U2.35(SCLK) ; off-sheet SPI1_CLK
SPI1_CS: U1.58(PB6) ; off-sheet SPI1_CS
SPI1_MISO: U1.59(PB7) U2.33(SDO) ; off-sheet SPI1_MISO
SPI1_MOSI: U1.60(PB8) U2.34(SDI) ; off-sheet SPI1_MOSI
STB: U1.34(PA1) ; off-sheet STB
STEP: TP8.1 U1.22(PB23) U3.11(STEP) ; off-sheet STEP
STEP_VREF: U1.8(PA15/A1_0) U3.7(VREF) ; off-sheet STEP_VREF
TCLK: J2.4 U1.13(PA20/SWCLK) ; off-sheet TCLK
TMAG_INT: U1.53(PB5) ; off-sheet TMAG_INT
TMP_IN: U1.9(PA16/A1_1) ; off-sheet TMP_IN
TMS: J2.2 U1.12(PA19/SWDIO) ; off-sheet TMS
TXD: U1.30(PA26/A0_1/CAN_TX) ; off-sheet TXD
UART_RX: U1.57(PA11) ; off-sheet UART_RX
UART_TX: U1.56(PA10) ; off-sheet UART_TX
V_Ctrl: U1.27(PB25/A0_4) ; off-sheet V_Ctrl
NetC4_1: C4.1 C5.1 J1.2 R5.2 U1.40(VDD)
NetC7_1: C7.1 U1.32(VCORE)
NetC9_1: C9.1 R46.2 U1.24(PA23/VREF+)
NetC10_2: C10.2(ANODE) C11.1 J3.2 U3.15(VM)
NetC12_2: C12.2 C14.1 C17.1 C53.2 J4.2 U2.9(VM) U2.10(VM) U2.11(VM)
NetC13_1: C13.1 U3.6(DVDD)
NetC16_1: C16.1 U2.7(CPH)
NetC16_2: C16.2 U2.6(CPL)
NetC17_2: C17.2 U2.8(CP)
NetC18_1: C18.1 U2.37(VREF/ILIM)
NetD1_2: D1.2(K) R1.2
NetD5_2: D5.2(K) R40.2
NetD6_2: D6.2(K) R43.2
NetL1_1: L1.1 U2.5(SW_BK)
NetQ1_1: Q1.1(B) R2.2 R3.2
NetQ1_3: Q1.3(C) R1.1
NetQ2_1: Q2.1(B) R41.2 R42.2
NetQ2_3: Q2.3(C) R40.1
NetQ3_1: Q3.1(B) R44.2 R45.2
NetQ3_3: Q3.3(C) R43.1
NetR3_1: R3.1 U1.49(PA7)
NetR4_1: R4.1 U1.42(PA2/ROSC)
NetR6_2: R6.2 R7.2 U3.8(M0)
NetR8_2: R8.2 R12.2 U3.10(M1)
NetR9_2: R9.2 U2.28(INLA)
NetR10_2: R10.2 U2.30(INLB)
NetR11_2: R11.2 U2.32(INLC)
NetR13_2: R13.2 TP7.1 U2.22(~{FAULT})
NetR14_1: R14.1 U2.40(SOA)
NetR15_1: R15.1 U2.39(SOB)
NetR16_1: R16.1 U2.38(SOC)
NetR42_1: R42.1 U1.63(PB11)
NetR45_1: R45.1 U1.62(PB10)
NetR53_1: R53.1 TP11.1 U1.11(PA18/A1_3)

Not connected (* = marked no-connect by the designer): J2 6* 8*; U1 21(PB22) 47(PB0) 54(PA8) 61(PB9); U2 1(NC)* 24(NC)*

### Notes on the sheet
- (near R16) 200mA MAX

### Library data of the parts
C1-C3 C6 = CMP-0006439-2: CAP, CERM, 22 pF, 50 V, +/- 5%, C0G/NP0, 0402; Manufacturer: MuRata; TaMin_C: -55°C; Polarized: N; SizeAreaWB_mm2: 3; Value1: Unknown; U/M: EA; Value: 22pF; TaMax_C: 125°C; SizeZ_mm: 0.6; SizeX_mm: 1; SizeY_mm: 0.5; AEC Category: Q200
C4 = CMP-0007304-5: CAP, CERM, 10 uF, 6.3 V, +/- 20%, X5R, 0603; Manufacturer: MuRata; TaMin_C: -55°C; Polarized: N; SizeAreaWB_mm2: 4.68; Value1: Unknown; U/M: EA; Value: 10uF; TaMax_C: 85°C; SizeZ_mm: 1; SizeX_mm: 1.6; SizeY_mm: 0.8; SizeArea_mm2: 1.28; Cap_F: 10µF; AEC Category: Q200
C5 C18 = CMP-0006531-2: CAP, CERM, 0.1 uF, 6.3 V, +/- 10%, X5R, 0402; Manufacturer: MuRata; TaMin_C: -55°C; Polarized: N; SizeAreaWB_mm2: 3; Value1: Unknown; U/M: EA; Value: 0.1uF; TaMax_C: 85°C; SizeZ_mm: 0.6; SizeX_mm: 1; SizeY_mm: 0.5; Cap_F: 100nF; AEC Category: Q200
C7 = CMP-0006551-2: CAP, CERM, 0.47 uF, 6.3 V, +/- 10%, X5R, 0402; Manufacturer: MuRata; TaMin_C: -55°C; Polarized: N; SizeAreaWB_mm2: 3; Value1: Unknown; U/M: EA; Value: 0.47uF; TaMax_C: 85°C; SizeZ_mm: 0.6; SizeX_mm: 1; SizeY_mm: 0.5; Cap_F: 470nF; AEC Category: Q200
C8 = CMP-0006530-2: CAP, CERM, 0.01 uF, 6.3 V, +/- 10%, X5R, 0402; Manufacturer: MuRata; TaMin_C: -55°C; Polarized: N; SizeAreaWB_mm2: 3; Value1: Unknown; U/M: EA; Value: 0.01uF; TaMax_C: 85°C; SizeZ_mm: 0.6; SizeX_mm: 1; SizeY_mm: 0.5; Cap_F: 10nF; AEC Category: Q200
C9 = CMP-0007006-5: CAP, CERM, 1 uF, 25 V, +/- 10%, X5R, 0603; Manufacturer: TDK; TaMin_C: -55°C; Polarized: N; SizeAreaWB_mm2: 4.68; Value1: Unknown; U/M: EA; Value: 1uF; TaMax_C: 85°C; SizeZ_mm: 1; SizeX_mm: 1.6; SizeY_mm: 0.8; SizeArea_mm2: 1.28; Cap_F: 1µF; AEC Category: Q200
C10 = CMP-0093755-1: Aluminum Electrolytic Capacitors Radial, Can - SMD 2.321Ohm @ 120Hz 2000 Hrs @ 105°C; Manufacturer: Cornell Dubilier; IRMS_A: 300mA; Leakage Current: 50uA; Life: 2000Hours; Value: 100µF; AEC Qualified: No; Tolerance_%: 20%; Esr: 2.321; SizeZ_mm: 10.6mm
C11 C14 = CMP-0007010-5: CAP, CERM, 0.1 uF, 50 V, +/- 10%, X5R, 0603; Manufacturer: TDK; TaMin_C: -55°C; ESR_ohm: 29.6m; Polarized: N; SizeAreaWB_mm2: 4.68; Value1: 0.0296 ohm; U/M: EA; Value: 0.1uF; TaMax_C: 85°C; SizeZ_mm: 1; SizeX_mm: 1.6; SizeY_mm: 0.8; SizeArea_mm2: 1.28; Cap_F: 100nF; IRMS_A: 971.99mA; AEC Category: Q200
C12 C53 = CMP-0095280-1: Chip Multilayer Ceramic Capacitors for General Purpose, 0805, 10uF, X5R, 15%, 20%, 50V; Manufacturer: Murata; Cap_F: 10µF; AEC Qualified: No; SizeZ_mm: 1.45mm; Value: 10µF
C13 = CMP-0007364-4: CAP, CERM, 0.47 uF, 6.3 V, +/- 10%, X7R, 0603; Manufacturer: MuRata; TaMin_C: -55°C; Polarized: N; SizeAreaWB_mm2: 4.68; Value1: Unknown; U/M: EA; Value: 0.47uF; TaMax_C: 125°C; SizeZ_mm: 1; SizeX_mm: 1.6; SizeY_mm: 0.8; SizeArea_mm2: 1.28; AEC Category: Q200
C15 = CMP-0006532-2: CAP, CERM, 1 uF, 6.3 V, +/- 10%, X5R, 0402; Manufacturer: MuRata; TaMin_C: -55°C; Polarized: N; SizeAreaWB_mm2: 3; Value1: Unknown; U/M: EA; Value: 1uF; TaMax_C: 85°C; SizeZ_mm: 0.6; SizeX_mm: 1; SizeY_mm: 0.5; Cap_F: 1µF; AEC Category: Q200
C16 = CMP-0006617-2: CAP, CERM, 0.047 uF, 50 V, +/- 20%, X5R, 0402; Manufacturer: MuRata; TaMin_C: -55°C; Polarized: N; SizeAreaWB_mm2: 3; Value1: Unknown; U/M: EA; TaMax_C: 85°C; SizeZ_mm: 0.6; SizeX_mm: 1; SizeY_mm: 0.5; Value2: 50V; Cap_F: 47nF; AEC Category: Q200
C17 = CMP-0006868-5: CAP, CERM, 1 uF, 16 V, +/- 10%, X5R, 0603; Manufacturer: Kemet; TaMin_C: -55°C; Polarized: N; SizeAreaWB_mm2: 4.68; Value1: Unknown; U/M: EA; Value: 1uF; TaMax_C: 85°C; SizeZ_mm: 1; SizeX_mm: 1.6; SizeY_mm: 0.8; SizeArea_mm2: 1.28; Cap_F: 1µF; AEC Category: Q200
C19 = CMP-0860267-1: CAP, CERM, 22 µF, 35 V,+/- 20%, X5R, 0805; Manufacturer: Arrow; TaMin_C: -55°C; SizeAreaWB_mm2: 6.75; U/M: EA; SizeZ_mm: 1.45; SizeArea_mm2: 2.5; SizeX_mm: 2; AEC Category: Q200; TaMax_C: 85°C; AEC Qualified: N; Cap_Case: 0805; Value: 22uF; SizeY_mm: 1.25
C20-C22 = CMP-0007205-4: CAP, CERM, 30 pF, 50 V, +/- 5%, C0G/NP0, 0603; Manufacturer: MuRata; TaMin_C: -55°C; Polarized: N; SizeAreaWB_mm2: 4.68; Value1: Unknown; U/M: EA; Value: 30pF; TaMax_C: 125°C; SizeZ_mm: 1; SizeX_mm: 1.6; SizeY_mm: 0.8; SizeArea_mm2: 1.28; AEC Category: Q200
C23-C25 = CMP-0006826-4: CAP, CERM, 1000 pF, 16 V, +/- 10%, X7R, 0603; Manufacturer: Wurth Elektronik; TaMin_C: -55°C; Polarized: N; SizeAreaWB_mm2: 4.68; Value1: Unknown; U/M: EA; Value: 1000pF; TaMax_C: 125°C; SizeZ_mm: 1; SizeX_mm: 1.6; SizeY_mm: 0.8; Cap_Case: 0603; SizeArea_mm2: 1.28; AEC Category: Q200
D1 = CMP-0002891-3: LED, Green, SMD; Manufacturer: Lite-On; Vf_V: 3.2V; Io_A: 20mA; Type: InGaN; Value1: W
D5 = CMP-0002950-3: as D4 on sheet Power
D6 = CMP-0002952-2: LED, Orange, SMD; Manufacturer: Lite-On; Io_A: 20mA; Power_TotalModule: 75mW; Vr_V: 5V; Tjmax_C: 85°C; Value1: 0.075W; U/M: EA; Angle: 130; Ir_A: 10µA; Vf_V: 2V; Type: AlInGaP
J1 J3 J4 = CMP-0075288-1: as J17 on sheet Power
J2 = CMP-0075670-2: Header (Shrouded), 1.27mm, 5x2, Gold, SMT; Manufacturer: Samtec; Pitch_mm: 1.27; Gender: Male; Cert_CSA: Y; Current_A: 3.3A; Row_Count: 2
J5 J6 = CMP-0055505-1: Terminal Block, 2x1, 6.35mm, Green, TH; Manufacturer: Phoenix Contact; CNHeader: FALSE; Shrouded: Y; Gender: Female; Row_Count: 1; Pitch_mm: 6.35; CT: TRUE
J7 = CMP-0055483-1: Terminal Block, 3x1, 6.35 mm, TH; Manufacturer: Phoenix Contact; CT: TRUE; CNHeader: FALSE
J8 = CMP-0055532-1: Terminal Block, 5mm, 5x1, R/A, TH; Manufacturer: Phoenix Contact; Cert_VDE: Y; CNHeader: FALSE; Current_A: 16A; Gender: Female; Voltage_V: 400V; Row_Count: 1; Pitch_mm: 5; CT: TRUE
L1 = CMP-0059315-2: Inductor, Drum Core, Ferrite, 47 uH, 0.2 A, 1.5 ohm, SMD; Manufacturer: NIC Components; Isat: 0.2A @ 30% inductance drop; Irms: 0.2A @ 40C rise; Green_Lifecycle: Active; SizeAreaWB_mm2: 18; DCR_ohm: 1.5; Green_REACh: Passed; Value1: 1.5 ohm; Value: 47uH; Imax_A: 200mA; SizeZ_mm: 2.4; SizeX_mm: 3.5; SizeY_mm: 3; Value2: 0.2A; SizeArea_mm2: 10.5; Ind_H: 47µH; AEC Category: Q200
Q1-Q3 = CMP-0000461-2: Transistor, NPN, 40 V, 0.6 A, SOT-23; Manufacturer: ON Semiconductor; TaMax_C: 150°C; Value1: 0.6 A; Vcesat1_V: 1V; SizeX_mm: 2.5; SizeY_mm: 3; TaMin_C: -55°C; IcRated_A: 600mA; CompType: BJT; SizeZ_mm: 1.1; Value: 40 V; SizeArea_mm2: 7.5; NPN: 1; Vceo_V: 40V; PNP: 0; AEC Category: Q101; SizeAreaWB_mm2: 14; U/M: EA
R1 = CMP-0027294-2: RES, 100, 1%, 0.05 W, 0201; Manufacturer: Yageo America; Power_W: 50mW; TempCo: 200 ppm/C; Value_Code: 100R; U/M: EA; Value: 100; EIA_Code: E96; SizeX_mm: 0.6; SizeY_mm: 0.3; SizeZ_mm: 0.26; Value2: 0.05W; SizeArea_mm2: 0.18; AEC Qualified: N; VDC_V: 25V; AEC Category: Q200
R2 R41 R44 = CMP-0028069-1: RES, 100 k, 1%, 0.05 W, 0201; Manufacturer: Yageo America; Power_W: 50mW; TempCo: 200 ppm/C; U/M: EA; Value: 100k; EIA_Code: E96; SizeX_mm: 0.6; SizeY_mm: 0.3; SizeZ_mm: 0.26; Value2: 0.05W; SizeArea_mm2: 0.18; AEC Qualified: N; VDC_V: 25V; AEC Category: Q200
R3 R42 R45 = CMP-0027131-1: RES, 4.7 k, 5%, 0.05 W, 0201; Manufacturer: Yageo America; Power_W: 50mW; TempCo: 200 ppm/C; Value_Code: 4k70; U/M: EA; Value: 4.7k; EIA_Code: E24; SizeX_mm: 0.6; SizeY_mm: 0.3; SizeZ_mm: 0.26; Value2: 0.05W; SizeArea_mm2: 0.18; AEC Qualified: N; VDC_V: 25V; AEC Category: Q200
R4 = CMP-0023630-3: RES, 100 k, 0.1%, 0.1 W, 0603; Manufacturer: Yageo America; Power_W: 100mW; TempCo: 25 ppm/C; U/M: EA; Value: 100k; EIA_Code: E192; SizeX_mm: 1.6; SizeY_mm: 0.8; SizeZ_mm: 1; Value2: 0.1W; SizeArea_mm2: 1.28; VDC_V: 75V; AEC Category: Q200
R5 = CMP-0026935-3: RES, 47 k, 5%, 0.063 W, AEC-Q200 Grade 0, 0402; Manufacturer: Vishay-Dale; Power_W: 63mW; TempCo: 200 ppm/C; Value_Code: 47k0; Value: 47k; EIA_Code: E24; SizeX_mm: 1; SizeY_mm: 0.5; SizeZ_mm: 0.6; Value2: 0.063W; AEC Qualified: Y; VDC_V: 50V; AEC Category: Q200; AEC Grade: 0
R6-R12 = CMP-0025697-4: RES, 0, 5%, 0.1 W, AEC-Q200 Grade 0, 0603; Manufacturer: Vishay-Dale; Power_W: 100mW; TempCo: 200 ppm/C; Value_Code: 0000; Value: 0; EIA_Code: E24; SizeX_mm: 1.6; SizeY_mm: 0.8; SizeZ_mm: 1; Value2: 0.1W; SizeArea_mm2: 1.28; AEC Qualified: Y; VDC_V: 75V; AEC Category: Q200
R13 = CMP-0025830-4: RES, 5.1 k, 5%, 0.1 W, AEC-Q200 Grade 0, 0603; Manufacturer: Vishay-Dale; Power_W: 100mW; TempCo: 200 ppm/C; Value_Code: 5k10; Value: 5.1k; EIA_Code: E24; SizeX_mm: 1.6; SizeY_mm: 0.8; SizeZ_mm: 1; Value2: 0.1W; SizeArea_mm2: 1.28; AEC Qualified: Y; VDC_V: 75V; AEC Category: Q200; AEC Grade: 0
R14-R16 = CMP-0025729-4: RES, 1.0 k, 5%, 0.1 W, AEC-Q200 Grade 0, 0603; Manufacturer: Vishay-Dale; Power_W: 100mW; TempCo: 200 ppm/C; Value_Code: 1k00; Value: 1.0k; EIA_Code: E24; Res_ohm: 1k; SizeX_mm: 1.6; SizeY_mm: 0.8; SizeZ_mm: 1; Value2: 0.1W; SizeArea_mm2: 1.28; AEC Qualified: Y; VDC_V: 75V; AEC Category: Q200; AEC Grade: 0
R17-R19 R53 = CMP-0025686-1: RES, 10.0 k, 0.1%, 0.1 W, AEC-Q200 Grade 1, 0603; Manufacturer: Vishay-Dale; Power_W: 100mW; TempCo: 25 ppm/C; Value_Code: 10k0; U/M: EA; Value: 10.0k; EIA_Code: E192; Res_ohm: 10k; SizeX_mm: 1.6; SizeY_mm: 0.85; SizeZ_mm: 0.55; Value2: 0.1W; SizeArea_mm2: 1.36; AEC Qualified: Y; VDC_V: 75V; AEC Grade: 1; AEC Category: Q200
R40 R43 = CMP-0027526-1: RES, 261, 1%, 0.05 W, 0201; Manufacturer: Yageo America; Power_W: 50mW; TempCo: 200 ppm/C; Value_Code: 261R; U/M: EA; Value: 261; EIA_Code: E96; SizeX_mm: 0.6; SizeY_mm: 0.3; SizeZ_mm: 0.26; Value2: 0.05W; SizeArea_mm2: 0.18; AEC Qualified: N; VDC_V: 25V; AEC Category: Q200
R46 = CMP-0025885-5: RES, 0, 5%, 0.1 W, 0603; Manufacturer: Yageo; Power_W: 100mW; TempCo: 200 ppm/C; Value_Code: 0000; Value: 0; EIA_Code: E24; SizeX_mm: 1.6; SizeZ_mm: 1; Value2: 0.1W; SizeArea_mm2: 1.28; AEC Qualified: N; VDC_V: 75V; AEC Category: Q200; SizeY_mm: 0.8; SizeAreaWB_mm2: 4.68
TP1-TP8 TP13-TP15 = CMP-0055155-2: Test Point, Compact, Blue, TH; Manufacturer: Keystone Electronics; Green_Lifecycle: Active; CNHeader: FALSE; ContactFinish: Silver; CT: TRUE; Green_REACh: Passed
TP9 TP10 = CMP-0055138-2: as TP19 on sheet Power
TP11 = CMP-0055154-1: Test Point, Miniature, Blue, TH; Manufacturer: Keystone; CNHeader: FALSE; Green_Lifecycle: Active; Green_REACh: Passed; ContactFinish: Silver; CT: TRUE
U1 = CMP-0093960-1: Mixed-Signal Microcontrollers With CAN-FD Interface LQFP64; Manufacturer: Texas Instruments; Number Of I2C Channels: 2; Frequency_Fixed: 80MHz; Number Of Cores: 1; Number Of Pwm Channels: 14; Data Bus Width: 32bits; Standoff Height: 0.05mm; SizeZ_mm: 1.6mm; Number Of I/Os: 60; Memory Type: FLASH; Min Supply Voltage: 1.62V; Number Of Adc Channels: 16; Memory Size: 128KBytes; TJmax_C: +130°C; Number Of Uart Channels: 4; Number Of Timers/Counters: 7; Max Supply Voltage: 3.6V; TaMin_C: -40°C; Core Architecture: ARM Cortex-M0+; Interface: I2C,SPI,UART,CAN,LIN,IrDA,SMBus; Ram Size: 32KBytes; AEC Qualified: No; TaMax_C: +125°C
U2 = CMP-0096344-1: Three-Phase Integrated FET Motor Driver; Manufacturer: Texas Instruments; Min Supply Voltage: 4.5V; TaMin_C: -40°C; Number Of Outputs: 3; Standoff Height: 0mm; Max Supply Voltage: 35V; Nominal Supply Current: 1.5-19000uA; Switching Frequency: 400kHz; SizeZ_mm: 1mm; Motor Type: Brushless DC; AEC Qualified: No; TaMax_C: +125°C; TJmax_C: +150°C
U3 = CMP-0861028-1: Stepper Drivers With Integrated Current Sense, 1/256 Microstepping, STEP/DIR Interface and smart tune Technology, RTE0016J (WQFN-16); Manufacturer: Texas Instruments; CompType: IC; SizeZ_mm: 0.8; AEC Category: Q200; SizeX_mm: 3; SizeAreaWB_mm2: 16; AEC Qualified: N; SizeArea_mm2: 9
Y1 = CMP-0098168-2: Crystal 40MHz ±10ppm (Tol) ±20ppm (Stability) 12pF FUND 40Ohm 4-Pin Mini-CSMD T/R; Manufacturer: Seiko Epson; Esr: 40; AEC Qualified: No; SizeZ_mm: 0.6mm
Y2 = CMP-0004693-3: Crystal, 32.768 KHz, 12.5 pF, SMD; Manufacturer: Epson; TaMax_C: 85°C; TaMin_C: -40°C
